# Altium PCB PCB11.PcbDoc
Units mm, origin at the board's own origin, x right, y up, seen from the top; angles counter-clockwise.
Board outline 101.6 x 53.34 mm, 4 copper layers (TOP, GND, SIG, BOTTOM), stack 1.586 mm thick; 13 components, 243 nets, 142 pads, 0 vias.
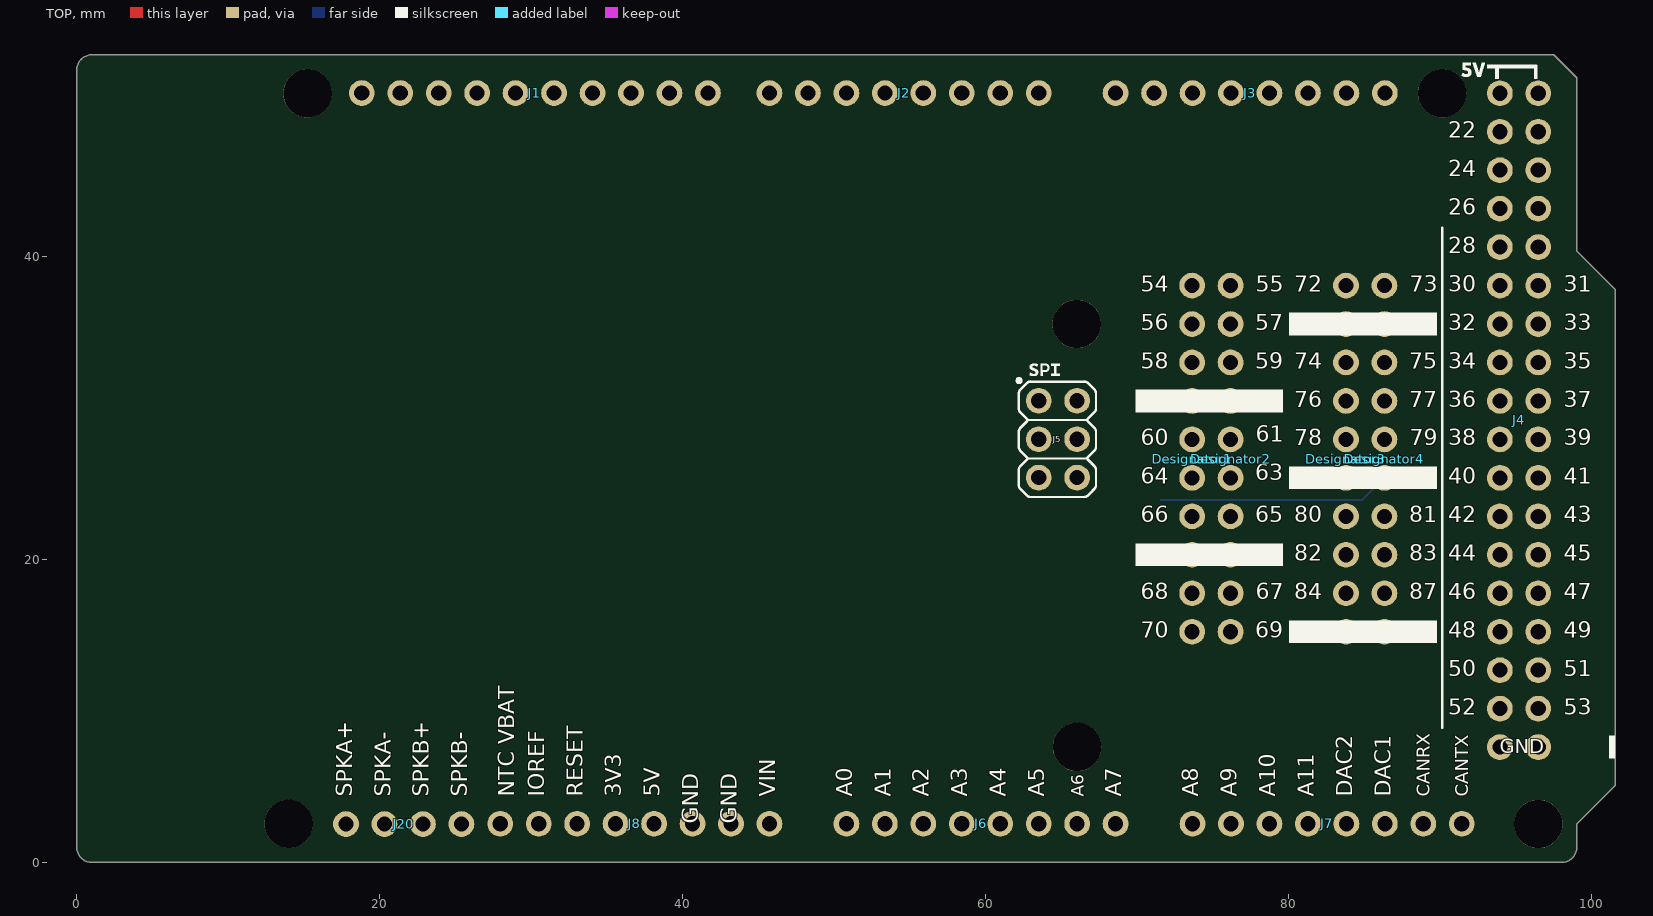
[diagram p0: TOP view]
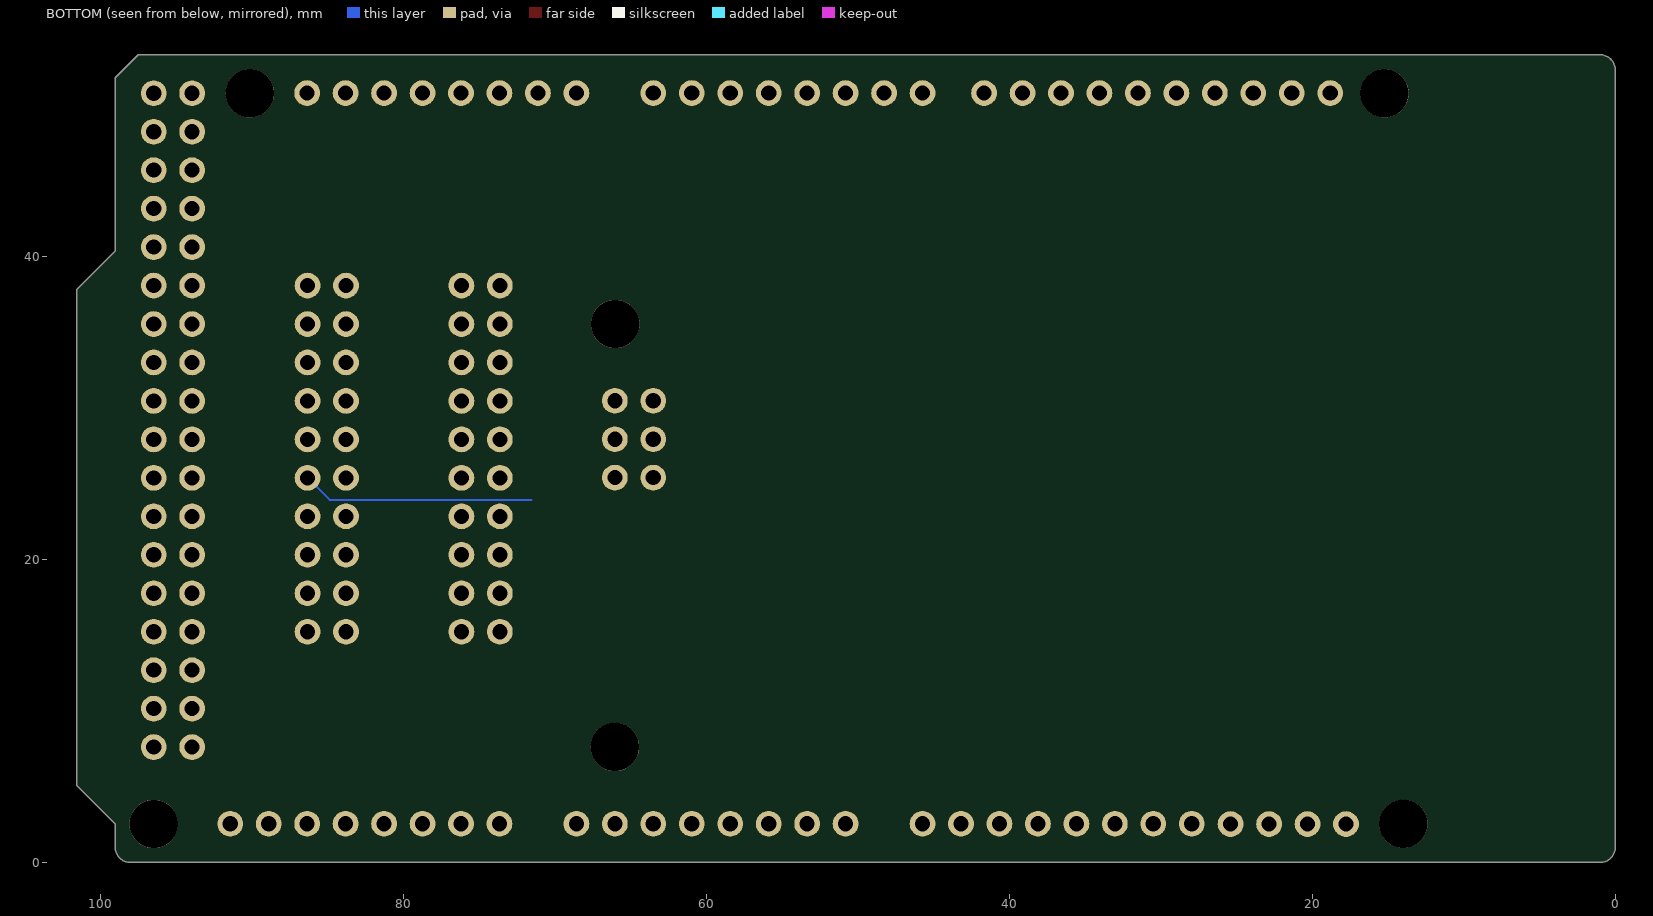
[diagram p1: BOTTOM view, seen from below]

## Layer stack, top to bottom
Top Solder: solder mask 0.0102, Solder Resist, Dk 3.5
TOP: signal copper 0.018
Dielectric 1: prepreg 0.14, PP-014, Dk 4.2
GND: signal copper 0.035
Dielectric2: core 1.2, FR-4, Dk 4.8
SIG: signal copper 0.035
Dielectric3: prepreg 0.14, PP-014, Dk 4.2
BOTTOM: signal copper 0.018
Bottom Solder: solder mask 0.0102, Solder Resist, Dk 3.5

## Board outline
0,1 0,52.34 cw(c1,52.34) 1,53.34 97.536,53.34 99.06,51.816 99.06,40.386 101.6,37.846 101.6,5.08 99.06,2.54 99.06,1 cw(c98.06,1) 98.06,0 1,0 cw(c1,1)

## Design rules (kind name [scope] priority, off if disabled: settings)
BoardOutlineClearance Silks [(OnLayer('Top Overlay') OR OnLayer('Bottom Overlay'))] p1: gap=0.1 ignorepadtopadclearanceinfootprint=FALSE
BoardOutlineClearance [All] p2: gap=0.3 ignorepadtopadclearanceinfootprint=FALSE
Clearance COPPER_0.3mm [All] p1: gap=0.127 ignorepadtopadclearanceinfootprint=FALSE except(0.3: Arc-Fill Arc-Poly Arc-Region Track-Fill Track-Poly Track-Region SMDPad-Fill SMDPad-Poly SMDPad-Region THPad-Fill THPad-Poly THPad-Region Via-Fill Via-Poly Via-Region Fill-Fill Fill-Poly Fill-Region Poly-Poly Poly-Region Region-Region)
Clearance "Generic clearance 0.127mm" [All] p2: gap=0.127 ignorepadtopadclearanceinfootprint=FALSE
ComponentClearance [All] p1: gap=0.2 collisioncheckmode=3 verticalgap=0 showdistances=TRUE
DiffPairsRouting USB [InDifferentialPairClass('USB')] p1: maxlimit=0.254 minlimit=0.15 mostfreqgap=0.254 toplayer_maxgap=0.15 toplayer_prefgap=0.15 toplayer_minwidth=0.15 toplayer_maxwidth=0.21 toplayer_prefwidth=0.2 midlayer2_mingap=0.24 midlayer2_maxgap=0.24 midlayer2_prefgap=0.24 midlayer2_minwidth=0.15 midlayer2_maxwidth=0.15 midlayer2_prefwidth=0.15 bottomlayer_maxgap=0.15 bottomlayer_prefgap=0.15 bottomlayer_minwidth=0.15 bottomlayer_maxwidth=0.21 bottomlayer_prefwidth=0.2 impedanceprofiledriven=TRUE impedanceprofileid={E6B00C31-4C8E-439C-824F-D2B2CDC26F9C} impedanceprofilevalue=90.000000 maxuncoupledlength=12.7
Height [All] p1: minheight=0 maxheight=30 prefheight=12.7
HoleSize [All] p1: absolutevalues=TRUE maxlimit=20 minlimit=0.3 maxpercent=80.000 minpercent=20.000
HoleToHoleClearance [All] p1: gap=0.25 allowstackedmicrovias=FALSE
MinimumAnnularRing [All] p1: minimumring=0.15
PlaneConnect [All] p1: pad.planeconnectstyle=Relief pad.reliefexpansion=0.508 pad.reliefentries=4 pad.reliefconductorwidth=0.254 pad.reliefairgap=0.254 via.planeconnectstyle=Direct via.reliefexpansion=0.508 via.reliefentries=4 via.reliefconductorwidth=0.254 via.reliefairgap=0.254
PolygonConnect [All] p1: thpad.connectstyle=Relief thpad.reliefconductorwidth=0.2 thpad.reliefentries=4 thpad.polygonreliefangle="90 Angle" thpad.airgapwidth=0.254 smdpad.connectstyle=Relief smdpad.reliefconductorwidth=0.2 smdpad.reliefentries=4 smdpad.polygonreliefangle="90 Angle" smdpad.airgapwidth=0.254 via.connectstyle=Direct via.reliefconductorwidth=0.254 via.reliefentries=4 via.polygonreliefangle="90 Angle" via.airgapwidth=0.254
RoomDefinition AUDIO [InComponentClass('AUDIO')] p1: confinementstyle=ConfineIn formatcopy=TRUE lockcomponents=FALSE outline 102.7,0.5 179.2,0.5 179.2,30 102.7,30
RoomDefinition Wifi [InComponentClass('Wifi')] p2: confinementstyle=ConfineIn formatcopy=TRUE lockcomponents=FALSE outline -40.4,-40.4 10.4,-40.4 10.4,-15 -40.4,-15
RoomDefinition TOP [InComponentClass('TOP')] p3: confinementstyle=ConfineIn formatcopy=TRUE lockcomponents=FALSE outline 102.7,1.5 112.4,1.5 112.4,12.5 102.7,12.5
RoomDefinition HEADERS [InComponentClass('HEADERS')] p4: confinementstyle=ConfineIn formatcopy=TRUE lockcomponents=FALSE outline 103.6,3.6 145.6,3.6 145.6,51.6 103.6,51.6
RoomDefinition STM32H747 [InComponentClass('STM32H747')] p5: confinementstyle=ConfineIn formatcopy=TRUE lockcomponents=FALSE outline 57.6,-10.4 61.6,-10.4 61.6,-6.4 57.6,-6.4
RoutingVias StandardVias [All] p1: holewidth=0.2 width=0.4 viastyle="Through Hole" minholewidth=0.2 minwidth=0.4 maxholewidth=0.2 maxwidth=0.4
SMDToCorner [All] p1: distance=39370
SilkToSilkClearance [All] p1: silktosilkclearance=0.2
SilkToSolderMaskClearance [IsPad] p1: minsilkscreentomaskgap=0.15 clearancetoexposedcopper=TRUE
SolderMaskExpansion VIAtented [IsVia] p1: expansion=0.102 istentingtop=TRUE
SolderMaskExpansion [All] p2: expansion=0.05 istentingtop=FALSE
UnRoutedNet [All] p1: checkbadconnections=TRUE
ViasUnderSMD [All] p1: allowed=FALSE
Width StandardTraces [All] p1: maxlimit=5 minlimit=0.127 preferedwidth=0.15
21 further rules are at their usual default settings.

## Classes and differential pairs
net class "50 ohm": NetC1V_1 NetC2V_1
component class Wifi: R18
component class HEADERS: J1 J2 J3 J4 J6 J7 J8 J20

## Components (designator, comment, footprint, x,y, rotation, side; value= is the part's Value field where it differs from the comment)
Designator1 "Comment" "PIN HEADER 2.54mm VERT. 1x10POS" 73.66,26.669 r270 top
Designator2 "Comment" "PIN HEADER 2.54mm VERT. 1x10POS" 76.2,26.669 r270 top
Designator3 "Comment" "PIN HEADER 2.54mm VERT. 1x10POS" 83.82,26.669 r270 top
Designator4 "Comment" "PIN HEADER 2.54mm VERT. 1x10POS" 86.36,26.669 r270 top
J1 "HEADER TH 2.54mm VERT. 1x010POS" "PIN HEADER 2.54mm VERT. 1x10POS" 30.252,50.813 r0 top
J2 "HEADER TH 2.54mm VERT. 1x008POS" "PIN HEADER 2.54mm VERT. 1x8POS" 54.636,50.813 r0 top
J3 "HEADER TH 2.54mm VERT. 1x008POS" "PIN HEADER 2.54mm VERT. 1x8POS" 77.496,50.813 r0 top
J4 "HEADER TH 2.54mm VERT. 2x018POS" "PIN HEADER 2.54mm VERT. 2x6POS" 95.25,29.209 r270 top
J5 "HEADER TH 2.54mm VERT. 2x003POS" "HEADER TH 2.54mm VERT. 2x003POS-Footprint-1" 64.796,27.953 r270 top
J6 "HEADER TH 2.54mm VERT. 1x008POS" "PIN HEADER 2.54mm VERT. 1x8POS" 59.716,2.553 r0 top
J7 "HEADER TH 2.54mm VERT. 1x008POS" "PIN HEADER 2.54mm VERT. 1x8POS" 82.576,2.553 r0 top
J8 "HEADER TH 2.54mm VERT. 1x008POS" "PIN HEADER 2.54mm VERT. 1x8POS" 36.856,2.553 r0 top
J20 "HEADER TH 2.54mm VERT. 1x004POS" "PIN HEADER 2.54mm VERT. 1x4POS-Footprint-1" 21.59,2.539 r0 top

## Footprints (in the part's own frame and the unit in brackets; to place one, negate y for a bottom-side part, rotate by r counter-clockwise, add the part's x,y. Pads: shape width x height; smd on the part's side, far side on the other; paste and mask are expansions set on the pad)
"HEADER TH 2.54mm VERT. 2x003POS-Footprint-1" [mm]
  round 1.7 hole 1 mask+0.2: 1(-2.54,-1.27) 2(-2.54,1.27) 3(0,-1.27) 4(0,1.27) 5(2.54,-1.27) 6(2.54,1.27)
"PIN HEADER 2.54mm VERT. 1x4POS-Footprint-1" [mm]
  round 1.7 hole 1 mask+0.2: 1(-3.81,0) 2(-1.27,0) 3(1.27,0) 4(3.81,0)
"PIN HEADER 2.54mm VERT. 1x8POS" [mm]
  round 1.7 hole 1 mask+0.2: 1(-8.89,0) 2(-6.35,0) 3(-3.81,0) 4(-1.27,0) 5(1.27,0) 6(3.81,0) 7(6.35,0) 8(8.89,0)
"PIN HEADER 2.54mm VERT. 1x10POS" [mm]
  round 1.7 hole 1 mask+0.2: 1(-11.43,0) 2(-8.89,0) 3(-6.35,0) 4(-3.81,0) 5(-1.27,0) 6(1.27,0) 7(3.81,0) 8(6.35,0) 9(8.89,0) 10(11.43,0)
"PIN HEADER 2.54mm VERT. 2x6POS" [mm]
  round 1.7 hole 1 mask+0.2: 1(-21.59,-1.27) 2(-21.59,1.27) 3(-19.05,-1.27) 4(-19.05,1.27) 5(-16.51,-1.27) 6(-16.51,1.27) 7(-13.97,-1.27) 8(-13.97,1.27) 9(-11.43,-1.27) 10(-11.43,1.27) 11(-8.89,-1.27) 12(-8.89,1.27) 13(-6.35,-1.27) 14(-6.35,1.27) 15(-3.81,-1.27) 16(-3.81,1.27) 17(-1.27,-1.27) 18(-1.27,1.27) 19(1.27,-1.27) 20(1.27,1.27) 21(3.81,-1.27) 22(3.81,1.27) 23(6.35,-1.27) 24(6.35,1.27) 25(8.89,-1.27) 26(8.89,1.27) 27(11.43,-1.27) 28(11.43,1.27) 29(13.97,-1.27) 30(13.97,1.27) 31(16.51,-1.27) 32(16.51,1.27) 33(19.05,-1.27) 34(19.05,1.27) 35(21.59,-1.27) 36(21.59,1.27)

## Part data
J1: library part J0169-A.5
J2 J3 J6 J7 J8: library part J0171-A.2
J4: library part J0239-A.1
J5: library part J0240-A.2
J20: library part J0162-A.4

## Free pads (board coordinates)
  round 3.2 hole 3.2 unplated: MH1(96.52,2.54) MH2(15.24,50.8) MH3(90.17,50.8) MH4(13.996,2.553) MH5(66.04,35.56) MH6(66.066,7.633)

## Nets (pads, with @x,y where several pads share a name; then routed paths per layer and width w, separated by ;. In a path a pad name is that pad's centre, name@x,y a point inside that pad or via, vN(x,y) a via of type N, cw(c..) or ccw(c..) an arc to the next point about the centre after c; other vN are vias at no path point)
+1V8: 
+3V1: 
+3V1SW: 
+3V3: 
AIN2A: 
AIN2B: 
AIN3A: 
AIN3B: 
BLE_CTRL_DEVICE_WAKE: 
BLE_CTRL_HOST_WAKE: 
BLE_CTRL_ON: 
DSI_CK_N: 
DSI_CK_P: 
DSI_D0_N: 
DSI_D0_P: 
DSI_D1_N: 
DSI_D1_P: 
GND: 
HP/LINE_OUTA: 
HP/LINE_OUTB: 
HSU_D_N: 
HSU_D_P: 
MICBIAS: 
NetAUDIO_RST_X: 
NetC1_2: 
NetC1V_1: 
NetC2V_1: 
NetC5V_1: 
NetC12_2: 
NetC30_2: 
NetC31_1: 
NetC31_2: 
NetC33_1: 
NetC46_1: 
NetC48_1: 
NetC49_1: 
NetC50_1: 
NetL1_2: 
NetL1V_1: 
NetR2_1: 
NetR3_1: 
NetR4_2: 
NetR6_1: 
NetR7_1: 
NetR8_2: 
NetR9_1: 
NetR10_2: 
NetR12_1: 
NetR34_2: 
NetR35_2: 
NetR46_1: 
NetR46_2: 
NetU1_J1: 
NetU1_K1: 
NetU1V_2: 
NetU1V_3: 
NetU1V_4: 
NetU1V_5: 
NetU1V_8: 
NetU1V_9: 
NetU1V_10: 
NetU1V_11: 
NetU1V_20: 
NetU1V_22: 
NetU1V_23: 
NetU1V_24: 
NetU1V_25: 
NetU1V_26: 
NetU1V_37: 
NetU2_37: 
NetU3_26: 
PA0: 
PA1: 
PA2: 
PA3: 
PA4: 
PA5: 
PA6: 
PA7: 
PA8: 
PA9: 
PA10: 
PA11: 
PA12: 
PA13: 
PA14: 
PA15: 
PB0: 
PB1: 
PB2: 
PB3: 
PB4: 
PB5: 
PB6: 
PB7: 
PB8: 
PB9: 
PB10: 
PB11: 
PB12: 
PB13: 
PB14: 
PB15: 
PC0: 
PC1: 
PC2: 
PC3: 
PC4: 
PC5: 
PC6: 
PC7: 
PC8: 
PC9: 
PC10: 
PC11: 
PC12: 
PC13: 
PD0: 
PD1: 
PD2: 
PD3: 
PD4: 
PD5: 
PD6: 
PD7: 
PD8: 
PD9: 
PD10: 
PD11: 
PD12: 
PD13: 
PD14: 
PD15: 
PE0: 
PE1: 
PE2: 
PE3: 
PE4: 
PE5: 
PE6: 
PE7: 
PE8: 
PE9: 
PE10: 
PE11: 
PE12: 
PE13: 
PE14: 
PE15: 
PF0: 
PF1: 
PF2: 
PF3: 
PF4: 
PF5: 
PF6: 
PF7: 
PF8: 
PF9: 
PF10: 
PF11: 
PF12: 
PF13: 
PF14: 
PF15: 
PG0: 
PG1: 
PG2: 
PG3: 
PG4: 
PG5: 
PG6: 
PG7: 
PG8: 
PG9: 
PG10: 
PG11: 
PG12: 
PG13: 
PG14: 
PG15: 
PH2: 
PH3: 
PH4: 
PH5: 
PH6: 
PH7: 
PH8: 
PH9: 
PH10: 
PH11: 
PH12: 
PH13: 
PH14: 
PH15: 
PI0: 
PI1: 
PI2: 
PI3: 
PI4: 
PI5: 
PI6: 
PI7: 
PI8: 
PI9: 
PI10: 
PI11: 
PI12: 
PI13: 
PI14: 
PI15: 
PJ0: 
PJ1: 
PJ2: 
PJ3: 
PJ4: 
PJ5: 
PJ6: 
PJ7: 
PJ8: 
PJ9: 
PJ10: 
PJ11: 
PJ12: 
PJ13: 
PJ14: 
PJ15: 
PK0: 
PK1: 
PK2: 
PK3: 
PK4: 
PK5: 
PK6: 
PK7: 
SPKR/HP: 
USB0_D_N: 
USB0_D_P: 
VCAP_A7: 
VCAP_D17: 
VCAP_U11: 
WIFI_CTRL_HOST_WAKE: 
WIFI_CTRL_ON: 
pads on no net: Designator1.1 Designator1.2 Designator1.3 Designator1.4 Designator1.5 Designator1.6 Designator1.7 Designator1.8 Designator1.9 Designator1.10 Designator2.1 Designator2.2 Designator2.3 Designator2.4 Designator2.5 Designator2.6 Designator2.7 Designator2.8 Designator2.9 Designator2.10 Designator3.1 Designator3.2 Designator3.3 Designator3.4 Designator3.5 Designator3.6 Designator3.7 Designator3.8 Designator3.9 Designator3.10 Designator4.1 Designator4.2 Designator4.3 Designator4.4 Designator4.5 Designator4.6 Designator4.7 Designator4.8 Designator4.9 Designator4.10 J1.1 J1.2 J1.3 J1.4 J1.5 J1.6 J1.7 J1.8 J1.9 J1.10 J2.1 J2.2 J2.3 J2.4 J2.5 J2.6 J2.7 J2.8 J3.1 J3.2 J3.3 J3.4 J3.5 J3.6 J3.7 J3.8 J4.1 J4.2 J4.3 J4.4 J4.5 J4.6 J4.7 J4.8 J4.9 J4.10 J4.11 J4.12 J4.13 J4.14 J4.15 J4.16 J4.17 J4.18 J4.19 J4.20 J4.21 J4.22 J4.23 J4.24 J4.25 J4.26 J4.27 J4.28 J4.29 J4.30 J4.31 J4.32 J4.33 J4.34 J4.35 J4.36 J5.1 J5.2 J5.3 J5.4 J5.5 J5.6 J6.1 J6.2 J6.3 J6.4 J6.5 J6.6 J6.7 J6.8 J7.1 J7.2 J7.3 J7.4 J7.5 J7.6 J7.7 J7.8 J8.1 J8.2 J8.3 J8.4 J8.5 J8.6 J8.7 J8.8 J20.1 J20.2 J20.3 J20.4
copper on no net: | length 15.4
  BOTTOM w0.127: 71.56,23.939 84.9,23.939 86.36,25.399

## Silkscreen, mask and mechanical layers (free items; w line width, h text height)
Top Overlay:
  drawing of 15 lines, arcs and shapes, not listed
  text "22" at 90.57,47.494 h1.8
  text "24" at 90.57,44.954 h1.8
  text "26" at 90.57,42.414 h1.8
  text "28" at 90.57,39.874 h1.8
  text "54" at 70.25,37.334 h1.8
  text "55" at 77.87,37.334 h1.8
  text "72" at 80.41,37.334 h1.8
  text "73" at 88.03,37.334 h1.8
  text "30" at 90.57,37.334 h1.8
  text "31" at 98.19,37.334 h1.8
  text "56" at 70.25,34.794 h1.8
  text "57" at 77.84,34.794 h1.8
  text "32" at 90.57,34.794 h1.8
  text "33" at 98.19,34.794 h1.8
  text "58" at 70.25,32.254 h1.8
  text "59" at 77.84,32.254 h1.8
  text "74" at 80.41,32.254 h1.8
  text "75" at 88,32.254 h1.8
  text "34" at 90.57,32.254 h1.8
  text "35" at 98.19,32.254 h1.8
  text "76" at 80.41,29.714 h1.8
  text "77" at 88,29.714 h1.8
  text "36" at 90.57,29.714 h1.8
  text "37" at 98.19,29.714 h1.8
  text "61" at 77.845,27.424 h1.8
  text "60" at 70.25,27.174 h1.8
  text "78" at 80.41,27.174 h1.8
  text "79" at 88.03,27.174 h1.8
  text "38" at 90.57,27.174 h1.8
  text "39" at 98.19,27.174 h1.8
  text "63" at 77.84,24.887 h1.8
  text "64" at 70.25,24.634 h1.8
  text "40" at 90.57,24.634 h1.8
  text "41" at 98.19,24.634 h1.8
  text "66" at 70.25,22.094 h1.8
  text "65" at 77.84,22.094 h1.8
  text "80" at 80.41,22.094 h1.8
  text "81" at 88,22.094 h1.8
  text "42" at 90.57,22.094 h1.8
  text "43" at 98.19,22.094 h1.8
  text "82" at 80.41,19.554 h1.8
  text "83" at 88,19.554 h1.8
  text "44" at 90.57,19.554 h1.8
  text "45" at 98.19,19.554 h1.8
  text "68" at 70.25,17.014 h1.8
  text "67" at 77.87,17.014 h1.8
  text "84" at 80.41,17.014 h1.8
  text "87" at 88,17.014 h1.8
  text "46" at 90.57,17.014 h1.8
  text "47" at 98.19,17.014 h1.8
  text "70" at 70.25,14.474 h1.8
  text "69" at 77.84,14.474 h1.8
  text "48" at 90.57,14.474 h1.8
  text "49" at 98.19,14.474 h1.8
  text "50" at 90.57,11.934 h1.8
  text "51" at 98.19,11.934 h1.8
  text "52" at 90.57,9.394 h1.8
  text "53" at 98.19,9.394 h1.8
  text "GND" at 93.98,6.869 h1.6
  text "SPKA+" at 18.545,4.349 h1.8 r90
  text "SPKA-" at 21.085,4.349 h1.8 r90
  text "SPKB+" at 23.625,4.349 h1.8 r90
  text "SPKB-" at 26.165,4.349 h1.8 r90
  text "NTC VBAT" at 29.243,4.349 h1.8 r90
  text "IOREF" at 31.245,4.349 h1.8 r90
  text "RESET" at 33.785,4.349 h1.8 r90
  text "3V3" at 36.325,4.349 h1.8 r90
  text "5V" at 38.865,4.349 h1.8 r90
  text "VIN" at 46.485,4.349 h1.8 r90
  text "A0" at 51.565,4.349 h1.8 r90
  text "A1" at 54.105,4.349 h1.8 r90
  text "A2" at 56.645,4.349 h1.8 r90
  text "A3" at 59.185,4.349 h1.8 r90
  text "A4" at 61.725,4.349 h1.8 r90
  text "A5" at 64.265,4.349 h1.8 r90
  text "A6" at 66.805,4.349 h1.4 r90
  text "A7" at 69.345,4.349 h1.8 r90
  text "A8" at 74.425,4.349 h1.8 r90
  text "A9" at 76.965,4.349 h1.8 r90
  text "A10" at 79.505,4.349 h1.8 r90
  text "A11" at 82.045,4.349 h1.8 r90
  text "DAC2" at 84.585,4.349 h1.8 r90
  text "DAC1" at 87.125,4.349 h1.8 r90
  text "CANRX" at 89.665,4.349 h1.5 r90
  text "CANTX" at 92.205,4.349 h1.5 r90
  text "GND" at 41.416,2.553 h1.8 r90
  text "GND" at 43.956,2.553 h1.8 r90
Route Tool Path:
  lines w2: -1,29.75 -1,22.47 -1,1 ccw(c1,1) 1,-1 42.3,-1 48.8,-1 ; -1,33.75 -1,40.25 -1,52.34 cw(c1,52.34) 1,54.34 41.52,54.34 48.8,54.34 ; 52.8,-1 60.08,-1 98.06,-1 ccw(c98.06,1) 100.06,1 100.06,2.126 102.307,4.373 ; 52.8,54.34 59.3,54.34 97.536,54.34 ; 102.6,19.096 102.6,12.596 102.6,5.08 ; 102.6,23.096 102.6,30.376 102.6,37.846 ; 97.536,54.34 cw(c97.536,53.34) 98.243,54.047 ; 97.536,54.34 cw(c97.536,53.34) 98.243,54.047 ; 98.243,54.047 99.767,52.523 ; 99.767,52.523 cw(c99.06,51.816) 100.06,51.816 ; 99.767,52.523 cw(c99.06,51.816) 100.06,51.816 ; 100.06,51.816 100.06,40.8 102.307,38.553 ; 102.307,4.373 ccw(c101.6,5.08) 102.6,5.08 ; 102.307,4.373 ccw(c101.6,5.08) 102.6,5.08 ; 102.307,38.553 cw(c101.6,37.846) 102.6,37.846 ; 102.307,38.553 cw(c101.6,37.846) 102.6,37.846
Board:
  the board outline again, w0.254
Mechanical 9:
  lines w0.1: 6.194,2.927 7.464,2.927 ; 7.464,1.657 7.464,2.927 ; 7.464,4.197 7.464,2.927 ; 8.734,2.927 7.464,2.927 ; 17.552,50.813 18.822,50.813 ; 18.822,49.543 18.822,50.813 ; 18.822,52.083 18.822,50.813 ; 20.092,50.813 18.822,50.813 ; 26.696,2.553 27.966,2.553 ; 27.966,1.283 27.966,2.553 ; 27.966,3.823 27.966,2.553 ; 29.236,2.553 27.966,2.553 ; 44.476,50.813 45.746,50.813 ; 45.746,49.543 45.746,50.813 ; 45.746,52.083 45.746,50.813 ; 47.016,50.813 45.746,50.813 ; 49.556,2.553 50.826,2.553 ; 50.826,1.283 50.826,2.553 ; 50.826,3.823 50.826,2.553 ; 52.096,2.553 50.826,2.553 ; 62.357,30.48 63.627,30.48 ; 63.627,29.21 63.627,30.48 ; 63.627,31.75 63.627,30.48 ; 64.897,30.48 63.627,30.48 ; 67.336,50.813 68.606,50.813 ; 68.606,49.543 68.606,50.813 ; 68.606,52.083 68.606,50.813 ; 69.876,50.813 68.606,50.813 ; 72.416,2.553 73.686,2.553 ; 73.686,1.283 73.686,2.553 ; 73.686,3.823 73.686,2.553 ; 74.956,2.553 73.686,2.553 ; 92.71,50.799 93.98,50.799 ; 93.98,49.529 93.98,50.799 ; 93.98,52.069 93.98,50.799 ; 95.25,50.799 93.98,50.799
